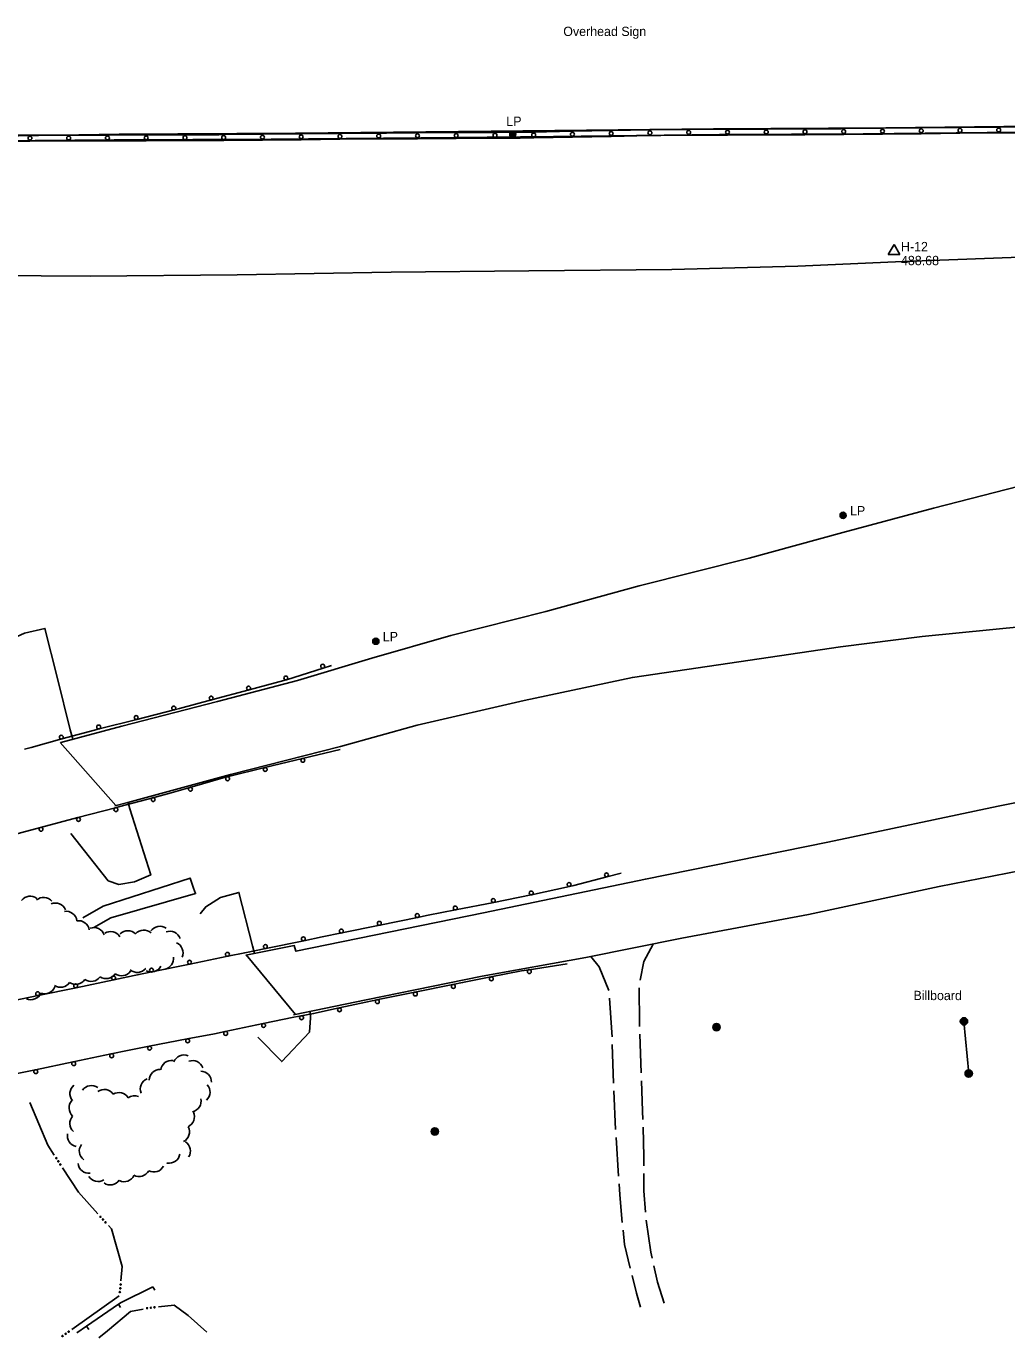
# Model space of a CAD drawing. Extents: x 2402803 to 2427059, y 6985292 to 6997652.
# Drawn here: x 2418486 to 2418992, y 6990807 to 6991484 of the extents above; entities that cross this region are included whole.
import ezdxf

# ---------------------------------------------------------------- set-up
doc = ezdxf.new("R2010")
doc.units = 0
for name, color, linetype in [('p_control ground ctrl', 7, 'Continuous'), ('p_drainage conc drain', 7, 'Continuous'), ('p_drainage earthen dam', 7, 'Continuous'), ('p_drainage riprap', 7, 'Continuous'), ('p_drainage water', 7, 'Continuous'), ('p_road - paved curb', 7, 'Continuous'), ('p_road bridge end', 7, 'Continuous'), ('p_road conc barrier', 7, 'Continuous'), ('p_road dirt road', 7, 'Continuous'), ('p_road guard rails', 7, 'Continuous'), ('p_structure general', 7, 'Continuous'), ('p_structure sign', 7, 'Continuous'), ('p_utility manhole', 7, 'Continuous'), ('p_veg woods', 7, 'Continuous'), ('V7 LEVEL 31', 7, 'Continuous')]:
    doc.layers.add(name, color=color, linetype=linetype)

msp = doc.modelspace()

# ---------------------------------------------------------------- linework, layer by layer
at = {"layer": 'p_control ground ctrl'}
for p, q in [((2418934.33, 6991371.33), (2418931.33, 6991366.13)), ((2418937.33, 6991366.13), (2418934.33, 6991371.33)), ((2418934.33, 6991367.85), (2418934.33, 6991367.89)), ((2418931.33, 6991366.13), (2418937.33, 6991366.13))]:
    msp.add_line(p, q, dxfattribs=at)
at = {"layer": 'p_drainage conc drain'}
msp.add_lwpolyline([(2418515.62, 6991023.78), (2418526.11, 6991029.78), (2418571.08, 6991044.2), (2418572.81, 6991039.08), (2418573.89, 6991036.24), (2418530.11, 6991023.72), (2418521.4, 6991018.74)], dxfattribs=at)
at = {"layer": 'p_drainage earthen dam'}
for p, q in [((2418551.87, 6990833.28), (2418552.76, 6990831.49)), ((2418534.06, 6990824.22), (2418517.57, 6990812.9)), ((2418534.06, 6990824.22), (2418535.19, 6990822.57)), ((2418517.57, 6990812.9), (2418512.51, 6990809.42)), ((2418517.57, 6990812.9), (2418518.71, 6990811.25))]:
    msp.add_line(p, q, dxfattribs=at)
msp.add_lwpolyline([(2418551.87, 6990833.28), (2418535.39, 6990825.13), (2418534.06, 6990824.22)], dxfattribs=at)
at = {"layer": 'p_drainage riprap'}
for points in [[(2418510.56, 6991115.87), (2418509.14, 6991120.82), (2418502.45, 6991147.97), (2418496.13, 6991173.11), (2418485.5, 6991170.75), (2418472.48, 6991164.79), (2418472.48, 6991164.76), (2418472.48, 6991164.76), (2418461.58, 6991155.58), (2418454.6, 6991145.01), (2418450.51, 6991136.17)], [(2418538.98, 6991083.31), (2418539.97, 6991079.92), (2418550.7, 6991045.85), (2418542.28, 6991042.37), (2418534.32, 6991040.99), (2418528.81, 6991042.83), (2418509.43, 6991067.24)], [(2418604.22, 6991005.28), (2418603.3, 6991009.21), (2418596.18, 6991036.85), (2418586.71, 6991034.19), (2418579.12, 6991029.4), (2418576.14, 6991025.78)], [(2418632.98, 6990975.47), (2418633.12, 6990972.11), (2418632.72, 6990964.77), (2418618.33, 6990949.5), (2418605.91, 6990962.16)]]:
    msp.add_lwpolyline(points, dxfattribs=at)
at = {"layer": 'p_drainage water'}
msp.add_line((2418534.42, 6990828.62), (2418509.96, 6990811.25), dxfattribs=at)
for points in [[(2418488.35, 6990928.46), (2418497.6, 6990906.31), (2418500.87, 6990901.28)], [(2418505.24, 6990894.58), (2418513.38, 6990882.07), (2418523.48, 6990870.88)], [(2418528.84, 6990864.94), (2418530.5, 6990863.1), (2418536.02, 6990843.69), (2418535.34, 6990836.38)], [(2418546.74, 6990821.73), (2418540.34, 6990820.56), (2418528.43, 6990810.49), (2418523.97, 6990806.93)], [(2418579.58, 6990809.78), (2418570.04, 6990818.46), (2418562.73, 6990823.68), (2418554.65, 6990822.83)]]:
    msp.add_lwpolyline(points, dxfattribs=at)
for centre in [(2418501.96, 6990899.61), (2418503.01, 6990898), (2418504.06, 6990896.39), (2418524.82, 6990869.4), (2418526.1, 6990867.97), (2418527.39, 6990866.55), (2418534.98, 6990832.48), (2418535.16, 6990834.39), (2418534.8, 6990830.57), (2418548.85, 6990822.23), (2418550.76, 6990822.43), (2418552.67, 6990822.63), (2418505.2, 6990807.86), (2418506.77, 6990808.98), (2418508.33, 6990810.09)]:
    msp.add_circle(centre, 0.3, dxfattribs=at)
at = {"layer": 'p_road - paved curb'}
for points in [[(2418329.91, 6991425.47), (2418376.12, 6991425.9), (2418451.16, 6991426.99), (2418534.43, 6991428.3), (2418625.37, 6991428.81), (2418726.33, 6991429.78), (2418841.22, 6991431.11), (2418930.03, 6991431.56), (2419021.5, 6991432.57), (2419118.7, 6991433.44), (2419214.1, 6991434.34), (2419288.84, 6991435.15), (2419366.26, 6991435.94), (2419398.65, 6991436)], [(2418330.64, 6991422.57), (2418376.33, 6991423.52), (2418450.16, 6991424.74), (2418531.75, 6991425.31), (2418612.82, 6991425.65), (2418690.12, 6991426.44), (2418758.52, 6991427.06), (2418844.23, 6991428.03), (2418918.44, 6991428.5), (2419014.37, 6991429.56), (2419095.43, 6991430.38), (2419192.72, 6991430.98), (2419279.92, 6991432.07), (2419356.93, 6991432.49), (2419397.76, 6991432.64)], [(2418350.28, 6991354.17), (2418373.03, 6991354.75), (2418443.52, 6991355.49), (2418519.5, 6991354.97), (2418595.24, 6991355.6), (2418674.87, 6991357.09), (2418745.82, 6991357.81), (2418819.67, 6991358.36), (2418884.66, 6991360.2), (2418935.13, 6991362.3), (2418994.78, 6991364.63), (2419091.42, 6991370.32), (2419171.78, 6991371.62), (2419248.3, 6991371.71), (2419311.63, 6991371.74), (2419369.32, 6991373.1), (2419402.63, 6991373.95)], [(2418504.29, 6991114.18), (2418535.86, 6991122.7), (2418585.17, 6991135.42), (2418626.44, 6991146.26), (2418664.78, 6991157.82), (2418705.59, 6991169.48), (2418754.62, 6991181.79), (2418802.74, 6991195.09), (2418859.57, 6991209.43), (2418907.85, 6991222.69), (2418954.63, 6991235.29), (2419011.63, 6991249.9), (2419067.67, 6991265.11), (2419127.27, 6991281.51), (2419182.52, 6991295.45), (2419230.28, 6991306.37), (2419304.04, 6991321.95), (2419358, 6991331.66), (2419405.74, 6991340.13)], [(2418532.12, 6991081.51), (2418538.81, 6991083.26), (2418591.89, 6991097.7), (2418648.61, 6991112.21), (2418688.15, 6991123.2), (2418743.5, 6991135.87), (2418799.33, 6991147.8), (2418843.66, 6991154.38), (2418906.7, 6991163.7), (2418948.89, 6991168.89), (2419002.64, 6991174.26), (2419064.17, 6991178.68), (2419120.57, 6991179.92), (2419181.48, 6991181.42), (2419241.1, 6991183.81), (2419326.04, 6991187.65), (2419399.52, 6991188.99)], [(2418599.73, 6991004.38), (2418624.74, 6991009.36), (2418625.61, 6991006.43), (2418722.39, 6991026.24), (2418806, 6991043.72), (2418900.21, 6991062.86), (2418988.09, 6991081.44), (2419064.29, 6991096.65), (2419133.65, 6991111.09), (2419230.01, 6991130.78), (2419299.54, 6991144.95), (2419360.7, 6991157.62), (2419406.64, 6991167.41)], [(2418624.38, 6990973.73), (2418661.87, 6990981.31), (2418721.79, 6990993.65), (2418775.18, 6991003.21), (2418824.86, 6991013.14), (2418890.12, 6991025.5), (2418957.56, 6991039.86), (2419028.22, 6991053.73), (2419103.48, 6991070.5), (2419160.2, 6991082.35), (2419242.4, 6991098.96), (2419306.15, 6991112.85), (2419352.29, 6991122.9), (2419406.69, 6991135.17)]]:
    msp.add_lwpolyline(points, dxfattribs=at)
at = {"layer": 'p_road bridge end'}
for points in [[(2418503.93, 6991114.27), (2418532.71, 6991081.77)], [(2418599.97, 6991004.59), (2418625.39, 6990973.81)]]:
    msp.add_lwpolyline(points, dxfattribs=at)
at = {"layer": 'p_road conc barrier'}
for p, q in [((2418488.37, 6991427.72), (2418508.37, 6991427.78)), ((2418508.37, 6991427.78), (2418528.37, 6991427.84)), ((2418528.37, 6991427.84), (2418548.37, 6991427.9)), ((2418548.37, 6991427.9), (2418568.37, 6991427.96)), ((2418588.35, 6991428.03), (2418608.35, 6991428.23)), ((2418608.35, 6991428.23), (2418628.34, 6991428.43)), ((2418628.34, 6991428.43), (2418648.34, 6991428.63)), ((2418648.34, 6991428.63), (2418668.34, 6991428.83)), ((2418688.36, 6991428.96), (2418708.36, 6991429.06)), ((2418708.36, 6991429.06), (2418728.36, 6991429.17)), ((2418748.31, 6991429.37), (2418768.31, 6991429.75)), ((2418768.31, 6991429.75), (2418788.3, 6991430.13)), ((2418788.3, 6991430.13), (2418808.3, 6991430.51)), ((2418788.36, 6991427.13), (2418808.36, 6991427.51)), ((2418828.34, 6991430.7), (2418848.34, 6991430.8)), ((2418828.36, 6991427.7), (2418848.36, 6991427.8)), ((2418848.34, 6991430.8), (2418868.34, 6991430.91)), ((2418848.36, 6991427.8), (2418868.36, 6991427.91)), ((2418868.34, 6991430.91), (2418888.34, 6991431.02)), ((2418868.36, 6991427.91), (2418888.35, 6991428.02)), ((2418908.32, 6991431.13), (2418928.32, 6991431.33)), ((2418908.35, 6991428.13), (2418928.35, 6991428.33)), ((2418928.32, 6991431.33), (2418948.32, 6991431.53)), ((2418928.35, 6991428.33), (2418948.35, 6991428.53)), ((2418948.32, 6991431.53), (2418968.32, 6991431.73)), ((2418948.35, 6991428.53), (2418968.35, 6991428.73)), ((2418968.32, 6991431.73), (2418988.32, 6991431.93)), ((2418968.35, 6991428.73), (2418988.35, 6991428.93)), ((2418488.38, 6991424.72), (2418508.38, 6991424.78)), ((2418508.38, 6991424.78), (2418528.38, 6991424.84)), ((2418528.38, 6991424.84), (2418548.38, 6991424.9)), ((2418548.38, 6991424.9), (2418568.38, 6991424.96)), ((2418588.38, 6991425.03), (2418608.38, 6991425.23)), ((2418608.38, 6991425.23), (2418628.37, 6991425.43)), ((2418628.37, 6991425.43), (2418648.37, 6991425.63)), ((2418648.37, 6991425.63), (2418668.37, 6991425.83)), ((2418688.37, 6991425.96), (2418708.37, 6991426.06)), ((2418708.37, 6991426.06), (2418728.37, 6991426.17)), ((2418748.37, 6991426.37), (2418768.37, 6991426.75)), ((2418768.37, 6991426.75), (2418788.36, 6991427.13))]:
    msp.add_line(p, q, dxfattribs=at)
for points in [[(2418468.31, 6991427.46), (2418478.59, 6991427.69), (2418488.37, 6991427.72)], [(2418568.37, 6991427.96), (2418585.85, 6991428.01), (2418588.35, 6991428.03)], [(2418668.34, 6991428.83), (2418672.34, 6991428.87), (2418688.36, 6991428.96)], [(2418728.36, 6991429.17), (2418741.29, 6991429.24), (2418748.31, 6991429.37)], [(2418808.3, 6991430.51), (2418813.97, 6991430.62), (2418828.34, 6991430.7)], [(2418808.36, 6991427.51), (2418814.01, 6991427.62), (2418828.36, 6991427.7)], [(2418888.34, 6991431.02), (2418907.15, 6991431.12), (2418908.32, 6991431.13)], [(2418888.35, 6991428.02), (2418907.17, 6991428.12), (2418908.35, 6991428.13)], [(2418988.32, 6991431.93), (2418999.89, 6991432.05), (2419008.32, 6991432.12)], [(2418988.35, 6991428.93), (2418999.91, 6991429.05), (2419008.35, 6991429.12)], [(2418468.38, 6991424.46), (2418478.63, 6991424.69), (2418488.38, 6991424.72)], [(2418568.38, 6991424.96), (2418585.87, 6991425.01), (2418588.38, 6991425.03)], [(2418668.37, 6991425.83), (2418672.36, 6991425.87), (2418688.37, 6991425.96)], [(2418728.37, 6991426.17), (2418741.33, 6991426.24), (2418748.37, 6991426.37)]]:
    msp.add_lwpolyline(points, dxfattribs=at)
for centre in [(2418568.37, 6991426.46), (2418588.36, 6991426.53), (2418608.36, 6991426.73), (2418628.36, 6991426.93), (2418648.36, 6991427.13), (2418668.36, 6991427.33), (2418688.36, 6991427.46), (2418708.36, 6991427.56), (2418728.36, 6991427.67), (2418748.34, 6991427.87), (2418768.34, 6991428.25), (2418788.33, 6991428.63), (2418808.33, 6991429.01), (2418828.35, 6991429.2), (2418848.35, 6991429.3), (2418868.35, 6991429.41), (2418888.35, 6991429.52), (2418908.34, 6991429.63), (2418928.34, 6991429.83), (2418948.34, 6991430.03), (2418968.34, 6991430.23), (2418988.34, 6991430.43), (2418488.37, 6991426.22), (2418508.37, 6991426.28), (2418528.37, 6991426.34), (2418548.37, 6991426.4)]:
    msp.add_circle(centre, 1, dxfattribs=at)
at = {"layer": 'p_road dirt road'}
for p, q in [((2418803.11, 6990963.63), (2418803.86, 6990943.64)), ((2418788.91, 6990958.35), (2418789.56, 6990938.36)), ((2418789.72, 6990934.37), (2418790.65, 6990914.39)), ((2418790.9, 6990910.4), (2418792.15, 6990890.44))]:
    msp.add_line(p, q, dxfattribs=at)
for points in [[(2418809.95, 6991010.16), (2418805.14, 6991001.22), (2418803.28, 6990991.56)], [(2418777.81, 6991003.74), (2418782.12, 6990998.35), (2418787.11, 6990986.28)], [(2418802.73, 6990987.62), (2418802.9, 6990969.29), (2418802.96, 6990967.62)], [(2418787.44, 6990982.3), (2418788.71, 6990964.46), (2418788.78, 6990962.35)], [(2418804, 6990939.64), (2418804.56, 6990923.85), (2418804.67, 6990919.66)], [(2418804.77, 6990915.66), (2418805.16, 6990900.34), (2418805.16, 6990895.67)], [(2418792.4, 6990886.44), (2418792.76, 6990880.71), (2418794.09, 6990866.52)], [(2418805.16, 6990891.67), (2418805.15, 6990882.82), (2418806.03, 6990871.7)], [(2418806.37, 6990867.72), (2418808.87, 6990851.09), (2418809.55, 6990847.98)], [(2418794.47, 6990862.53), (2418795.17, 6990855.02), (2418798.15, 6990842.93)], [(2418799.1, 6990839.05), (2418801.36, 6990829.87), (2418803.43, 6990822.81)], [(2418810.39, 6990844.07), (2418812.21, 6990835.71), (2418815.6, 6990824.78)]]:
    msp.add_lwpolyline(points, dxfattribs=at)
at = {"layer": 'p_road guard rails'}
for p, q in [((2418620.74, 6991146.58), (2418639.75, 6991152.65)), ((2418639.75, 6991152.65), (2418643.99, 6991154)), ((2418582.14, 6991136.18), (2418601.45, 6991141.35)), ((2418543.45, 6991126.16), (2418562.82, 6991131.05)), ((2418524.08, 6991121.27), (2418543.45, 6991126.16)), ((2418648.39, 6991110.65), (2418628.97, 6991105.99)), ((2418609.56, 6991101.25), (2418590.15, 6991096.5)), ((2418513.17, 6991075.47), (2418493.85, 6991070.39)), ((2418532.48, 6991080.56), (2418513.17, 6991075.47)), ((2418786.16, 6991044.91), (2418793.48, 6991046.82)), ((2418747.3, 6991035.59), (2418766.82, 6991039.95)), ((2418708.07, 6991027.82), (2418727.69, 6991031.71)), ((2418668.87, 6991019.9), (2418688.46, 6991023.91)), ((2418649.27, 6991015.9), (2418668.87, 6991019.9)), ((2418610.08, 6991007.91), (2418629.67, 6991011.9)), ((2418570.9, 6990999.83), (2418590.49, 6991003.89)), ((2418551.32, 6990995.76), (2418570.9, 6990999.83)), ((2418765.7, 6991000.02), (2418745.94, 6990996.96)), ((2418492.57, 6990983.57), (2418512.15, 6990987.64)), ((2418512.15, 6990987.64), (2418531.74, 6990991.7)), ((2418706.68, 6990989.28), (2418687.07, 6990985.37)), ((2418667.46, 6990981.43), (2418647.92, 6990977.19)), ((2418608.77, 6990969.12), (2418589.19, 6990965.04)), ((2418569.57, 6990961.19), (2418549.93, 6990957.42)), ((2418530.33, 6990953.5), (2418510.75, 6990949.4)), ((2418510.75, 6990949.4), (2418491.18, 6990945.29))]:
    msp.add_line(p, q, dxfattribs=at)
for points in [[(2418601.45, 6991141.35), (2418619.41, 6991146.16), (2418620.74, 6991146.58)], [(2418562.82, 6991131.05), (2418565.59, 6991131.75), (2418582.14, 6991136.18)], [(2418485.55, 6991110.79), (2418489.02, 6991111.73), (2418504.81, 6991116.05)], [(2418504.81, 6991116.05), (2418521.66, 6991120.66), (2418524.08, 6991121.27)], [(2418628.97, 6991105.99), (2418625.47, 6991105.15), (2418609.56, 6991101.25)], [(2418590.15, 6991096.5), (2418589.25, 6991096.28), (2418570.92, 6991091.07)], [(2418570.92, 6991091.07), (2418561.28, 6991088.33), (2418551.71, 6991085.74)], [(2418551.71, 6991085.74), (2418534.74, 6991081.15), (2418532.48, 6991080.56)], [(2418493.85, 6991070.39), (2418493.76, 6991070.37), (2418474.56, 6991065.17)], [(2418766.82, 6991039.95), (2418768.99, 6991040.43), (2418786.16, 6991044.91)], [(2418727.69, 6991031.71), (2418747.11, 6991035.55), (2418747.3, 6991035.59)], [(2418688.46, 6991023.91), (2418693.96, 6991025.03), (2418708.07, 6991027.82)], [(2418629.67, 6991011.9), (2418639.18, 6991013.84), (2418649.27, 6991015.9)], [(2418590.49, 6991003.89), (2418599.25, 6991005.71), (2418610.08, 6991007.91)], [(2418531.74, 6990991.7), (2418538.89, 6990993.18), (2418551.32, 6990995.76)], [(2418745.94, 6990996.96), (2418742.12, 6990996.37), (2418726.3, 6990993.2)], [(2418726.3, 6990993.2), (2418711.65, 6990990.27), (2418706.68, 6990989.28)], [(2418472.99, 6990979.51), (2418479.44, 6990980.85), (2418492.57, 6990983.57)], [(2418687.07, 6990985.37), (2418668.93, 6990981.75), (2418667.46, 6990981.43)], [(2418647.92, 6990977.19), (2418634.72, 6990974.32), (2418628.35, 6990973.12)], [(2418628.35, 6990973.12), (2418624.61, 6990972.42), (2418608.77, 6990969.12)], [(2418589.19, 6990965.04), (2418583.55, 6990963.87), (2418569.57, 6990961.19)], [(2418549.93, 6990957.42), (2418538.76, 6990955.27), (2418530.33, 6990953.5)], [(2418491.18, 6990945.29), (2418476.67, 6990942.25), (2418471.6, 6990941.21)]]:
    msp.add_lwpolyline(points, dxfattribs=at)
for centre in [(2418639.45, 6991153.6), (2418601.19, 6991142.32), (2418620.43, 6991147.54), (2418581.88, 6991137.15), (2418562.58, 6991132.02), (2418523.83, 6991122.24), (2418543.2, 6991127.13), (2418504.55, 6991117.01), (2418629.21, 6991105.02), (2418590.39, 6991095.53), (2418609.8, 6991100.28), (2418571.2, 6991090.11), (2418551.97, 6991084.78), (2418513.42, 6991074.51), (2418532.74, 6991079.59), (2418494.1, 6991069.43), (2418766.61, 6991040.92), (2418785.91, 6991045.88), (2418747.09, 6991036.57), (2418707.88, 6991028.8), (2418727.49, 6991032.69), (2418668.67, 6991020.88), (2418688.26, 6991024.89), (2418649.07, 6991016.88), (2418609.88, 6991008.89), (2418629.48, 6991012.88), (2418570.7, 6991000.8), (2418590.28, 6991004.87), (2418551.12, 6990996.74), (2418746.09, 6990995.97), (2418511.95, 6990988.61), (2418531.53, 6990992.68), (2418706.88, 6990988.3), (2418726.49, 6990992.22), (2418492.37, 6990984.55), (2418667.68, 6990980.45), (2418687.27, 6990984.39), (2418648.13, 6990976.21), (2418608.97, 6990968.14), (2418628.54, 6990972.14), (2418569.76, 6990960.2), (2418589.39, 6990964.06), (2418530.53, 6990952.52), (2418550.12, 6990956.43), (2418510.96, 6990948.42), (2418491.38, 6990944.31)]:
    msp.add_circle(centre, 1, dxfattribs=at)
at = {"layer": 'p_structure sign'}
msp.add_line((2418970.41, 6990970.26), (2418972.85, 6990943.35), dxfattribs=at)
for centre, radius in [((2418970.41, 6990970.26), 1.9), ((2418970.41, 6990970.26), 1.44), ((2418970.41, 6990970.26), 0.973), ((2418970.41, 6990970.26), 0.539), ((2418970.41, 6990970.26), 0.192), ((2418972.85, 6990943.35), 1.9), ((2418972.85, 6990943.35), 1.44), ((2418972.85, 6990943.35), 0.973), ((2418972.85, 6990943.35), 0.539), ((2418972.85, 6990943.35), 0.192)]:
    msp.add_circle(centre, radius, dxfattribs=at)
at = {"layer": 'p_utility manhole'}
for centre, radius in [((2418737.55, 6991428.25), 1.6), ((2418737.55, 6991428.25), 1.3), ((2418737.55, 6991428.25), 1), ((2418737.55, 6991428.25), 0.539), ((2418737.55, 6991428.25), 0.192), ((2418908.03, 6991231.49), 1.6), ((2418908.03, 6991231.49), 1.3), ((2418908.03, 6991231.49), 1), ((2418908.03, 6991231.49), 0.539), ((2418908.03, 6991231.49), 0.192), ((2418666.88, 6991166.52), 1.6), ((2418666.88, 6991166.52), 1.3), ((2418666.88, 6991166.52), 1), ((2418666.88, 6991166.52), 0.539), ((2418666.88, 6991166.52), 0.192), ((2418842.68, 6990967.31), 1.9), ((2418842.68, 6990967.31), 1.44), ((2418842.68, 6990967.31), 0.973), ((2418842.68, 6990967.31), 0.539), ((2418842.68, 6990967.31), 0.192), ((2418697.31, 6990913.45), 1.9), ((2418697.31, 6990913.45), 1.44), ((2418697.31, 6990913.45), 0.973), ((2418697.31, 6990913.45), 0.539), ((2418697.31, 6990913.45), 0.192)]:
    msp.add_circle(centre, radius, dxfattribs=at)
at = {"layer": 'p_veg woods'}
for centre, start, end in [((2418488.46, 6991029.25), 52.05389, 142.05389), ((2418495.4, 6991028.63), 40.16413, 130.16413), ((2418501.48, 6991025.72), 22.33533, 112.33533), ((2418507.01, 6991021.45), 7.99461, 97.99461), ((2418513.41, 6991016.6), 9.19067, 99.19067), ((2418521.41, 6991013.04), 19.8557, 109.8557), ((2418530.02, 6991010.98), 32.16047, 122.16047), ((2418538.99, 6991011.44), 45.83717, 135.83717), ((2418547.07, 6991011.74), 47.81602, 137.81602), ((2418555.37, 6991013.7), 55.05905, 145.05905), ((2418560.58, 6991011.15), 20.48251, 110.48251), ((2418561.71, 6991005.64), 336.36167, 66.36167), ((2418556.84, 6991002.8), 283.32846, 6.10837), ((2418527.72, 6990997.98), 235.60612, 325.60612), ((2418535.58, 6990999.45), 235.60406, 325.60406), ((2418543.72, 6991001.19), 231.10291, 321.10291), ((2418550.97, 6991001.42), 242.97656, 332.97656), ((2418496.02, 6990990.15), 248.33733, 338.33733), ((2418504.19, 6990993.51), 235.87568, 325.87568), ((2418512.02, 6990995.02), 235.73671, 325.73671), ((2418519.87, 6990996.51), 235.63174, 325.63174), ((2418488.82, 6990987.1), 246.57641, 336.57641), ((2418561.51, 6990944.5), 82.67769, 172.67769), ((2418567.93, 6990947.3), 68.06923, 158.06923), ((2418572.3, 6990944.37), 19.46007, 109.46007), ((2418550.98, 6990935.43), 112.7598, 202.7598), ((2418555.55, 6990939.85), 89.00104, 179.00104), ((2418576.41, 6990938.94), 358.66612, 88.66612), ((2418514.65, 6990932.95), 128.99927, 218.99927), ((2418520.17, 6990931.52), 55.47178, 145.47178), ((2418526.75, 6990929.45), 35.69831, 125.69831), ((2418534.31, 6990927.86), 31.88858, 121.88858), ((2418575.68, 6990933.8), 312.06197, 42.06197), ((2418514.18, 6990925.62), 138.20634, 228.20634), ((2418542.4, 6990926.22), 68.69126, 125.71149), ((2418571.06, 6990929.13), 282.60693, 12.60693), ((2418514.61, 6990917.61), 137.93901, 227.93901), ((2418567.6, 6990921.01), 294.60372, 24.60372), ((2418565.07, 6990913.25), 297.06103, 27.06103), ((2418513.34, 6990911.21), 168.95994, 258.95994), ((2418519.49, 6990903.32), 143.19324, 233.19324), ((2418565.55, 6990903.36), 326.8076, 56.8076), ((2418560.19, 6990902.72), 260.34237, 350.34237), ((2418518.82, 6990897.48), 185.91372, 275.91372), ((2418544.67, 6990895.79), 242.25185, 332.25185), ((2418552.3, 6990898.16), 242.25185, 332.25185), ((2418553.68, 6990898.11), 347.812, 350.34237), ((2418523.55, 6990893.21), 211.60574, 301.60574), ((2418529.76, 6990891.51), 235.85949, 325.85949), ((2418536.96, 6990893.15), 244.43829, 334.43829)]:
    msp.add_arc(centre, 5.65, start, end, dxfattribs=at)

# ---------------------------------------------------------------- texts
at = {"layer": 'p_control ground ctrl'}
msp.add_text('  H-12', height=4.8, dxfattribs=at).set_placement((2418934.33, 6991367.85))
at = {"layer": 'p_structure general'}
msp.add_text('Overhead Sign', height=4.8, dxfattribs=at).set_placement((2418763.6, 6991478.95))
at = {"layer": 'p_structure sign'}
msp.add_text('Billboard', height=4.8, dxfattribs=at).set_placement((2418944.35, 6990981.24))
at = {"layer": 'p_utility manhole'}
for p in [(2418730.65, 6991432.54), (2418908.03, 6991231.49), (2418666.88, 6991166.52)]:
    msp.add_text('  LP', height=4.8, dxfattribs=at).set_placement(p)
at = {"layer": 'V7 LEVEL 31'}
msp.add_text('  488.68', height=4.8, dxfattribs=at).set_placement((2418934.33, 6991360.65))

doc.saveas('drawing.dxf')
